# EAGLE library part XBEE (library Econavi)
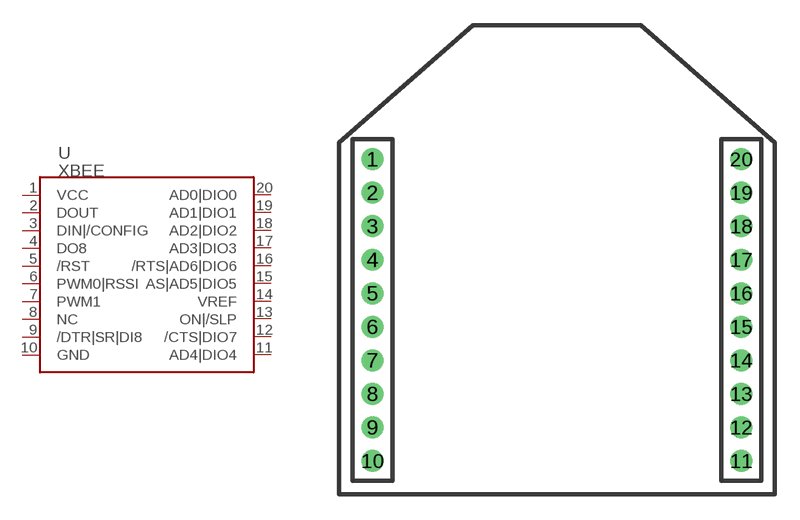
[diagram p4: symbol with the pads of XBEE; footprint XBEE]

Designator prefix U

## XBEE  [XBEE]
1  VCC  pwr
2  DOUT
3  DIN|/CONFIG  in
4  DO8
5  /RST  in
6  PWM0|RSSI
7  PWM1
8  NC  nc
9  /DTR|SR|DI8  in
10  GND  pwr
11  AD4|DIO4
12  /CTS|DIO7
13  ON|/SLP
14  VREF  in
15  AS|AD5|DIO5
16  /RTS|AD6|DIO6
17  AD3|DIO3
18  AD2|DIO2
19  AD1|DIO1
20  AD0|DIO0

## Footprint XBEE (pad centres in mm)
drill 0.8 round: 1 -11,9; 2 -11,7; 3 -11,5; 4 -11,3; 5 -11,1; 6 -11,-1; 7 -11,-3; 8 -11,-5; 9 -11,-7; 10 -11,-9; 11 11,-9; 12 11,-7; 13 11,-5; 14 11,-3; 15 11,-1; 16 11,1; 17 11,3; 18 11,5; 19 11,7; 20 11,9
